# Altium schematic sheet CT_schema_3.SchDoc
size 298 x 177 mm
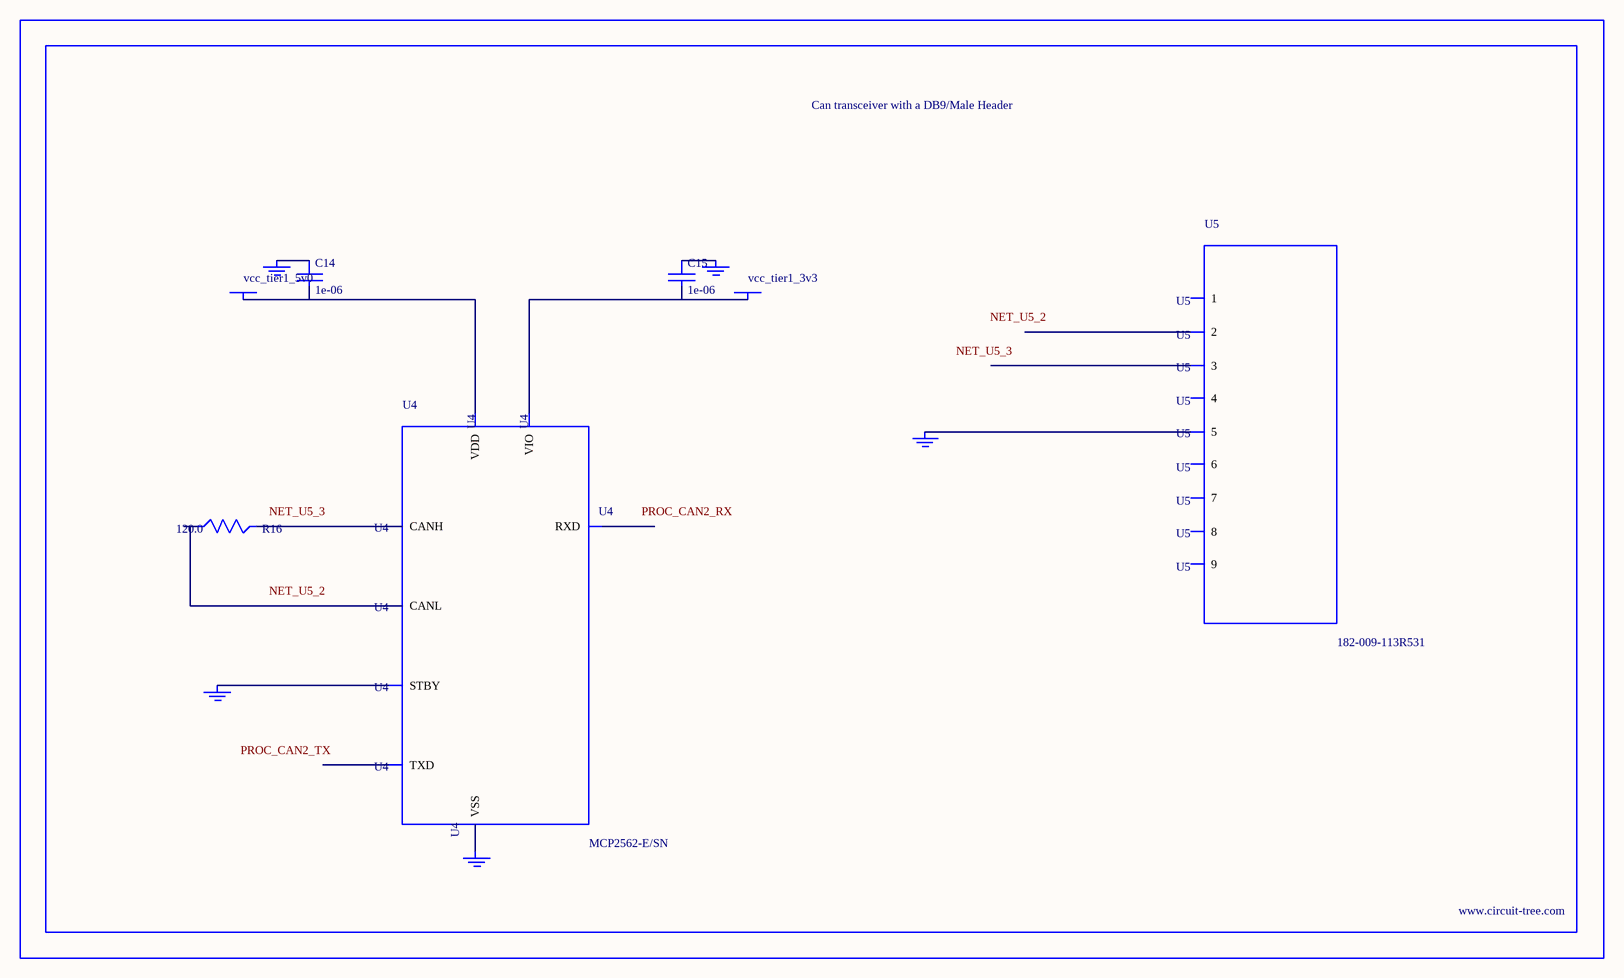
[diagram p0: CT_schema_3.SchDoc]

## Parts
BORDER2  (no value)
C14  1e-06  [C0603]
C15  1e-06  [C0603]
GND_INSTANCE_2_0  (no value)
GND_INSTANCE_2_1  (no value)
GND_INSTANCE_2_2  (no value)
GND_INSTANCE_2_3  (no value)
GND_INSTANCE_2_4  (no value)
POWER_INSTANCE_2_0  vcc_tier1_5v0
POWER_INSTANCE_2_1  vcc_tier1_3v3
R16  120.0  [R0603]
U4  MCP2562-E/SN  [SOIC-8]
U5  182-009-113R531  [182-009-MALE]

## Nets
NetC14_1: C14.1 GND_INSTANCE_2_0.0(GND)
NetC14_2: C14.2 POWER_INSTANCE_2_0.0(PWR) U4.3(VDD)
NetC15_1: C15.1 GND_INSTANCE_2_1.0(GND)
NetC15_2: C15.2 POWER_INSTANCE_2_1.0(PWR) U4.5(VIO)
NetGND_INSTANCE_2_2_0: GND_INSTANCE_2_2.0(GND) U4.8(STBY)
NetGND_INSTANCE_2_3_0: GND_INSTANCE_2_3.0(GND) U4.2(VSS)
NetGND_INSTANCE_2_4_0: GND_INSTANCE_2_4.0(GND) U5.5
NetR16_1: R16.1 U4.6(CANL)
NetR16_2: R16.2 U4.7(CANH)

Not connected (* = marked no-connect by the designer): U4 1(TXD) 4(RXD); U5 1 2 3 4 6 7 8 9

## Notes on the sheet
- Labels drawn without touching a wire or pin: NET_U5_2, NET_U5_3, PROC_CAN2_RX, PROC_CAN2_TX

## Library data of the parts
BORDER2 = BORDER_PAGE2
C14 C15 = C0603C105K3RACTU
GND_INSTANCE_2_0-GND_INSTANCE_2_4 = GND
POWER_INSTANCE_2_0 POWER_INSTANCE_2_1 = PWR
R16 = RC0603JR-07120RL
